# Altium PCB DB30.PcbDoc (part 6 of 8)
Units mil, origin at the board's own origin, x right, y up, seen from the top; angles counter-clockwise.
Board outline 3236.22 x 4456.69 mil, 8 copper layers (Top Layer, MidLayer1, MidLayer2, GND-Layer5, MidLayer3, VCC, MidLayer4, Bottom Layer), stack 61.8 mil thick; 219 components, 472 nets, 1811 pads, 1561 vias.
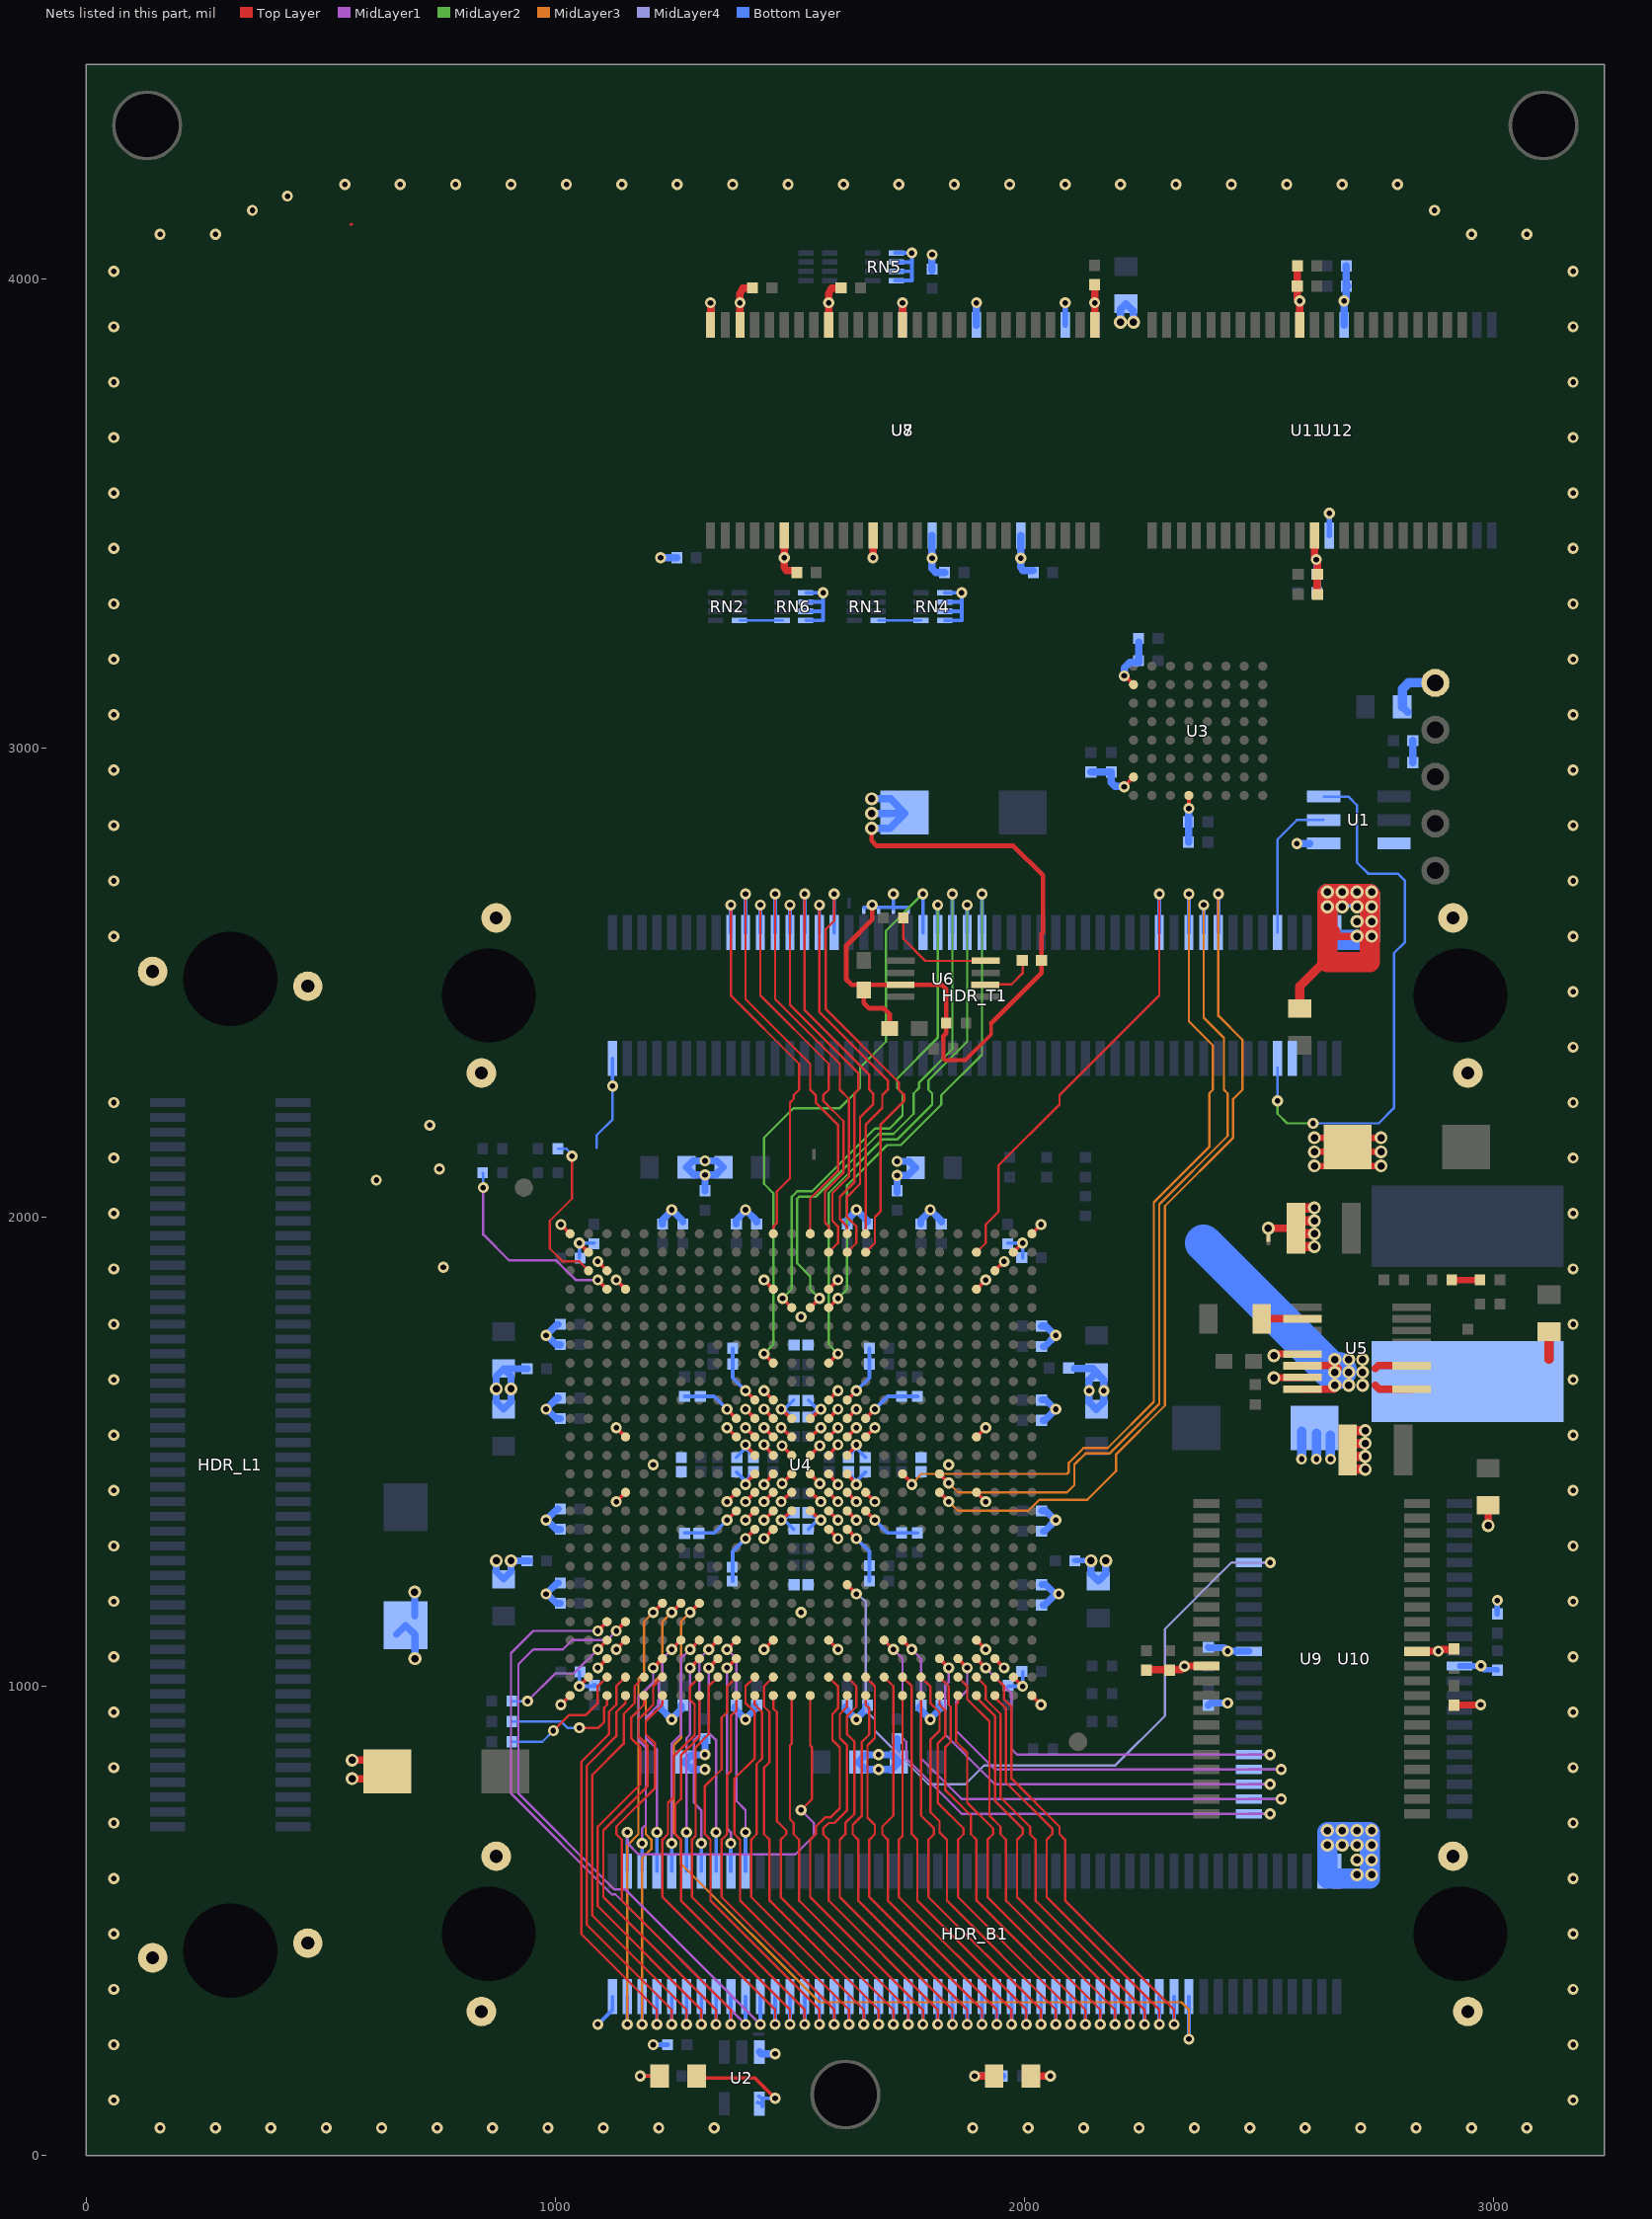
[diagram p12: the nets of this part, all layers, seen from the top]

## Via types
v1: diameter 23.62, hole 11.81, Top Layer to Bottom Layer, 944 vias
v2: diameter 23.62, hole 11.81, Top Layer to Bottom Layer, tented both sides, 477 vias
v3: diameter 27.56, hole 15.75, Top Layer to Bottom Layer, 139 vias
v4: diameter 23.62, hole 11.81, Top Layer to Bottom Layer, tented top, 1 vias

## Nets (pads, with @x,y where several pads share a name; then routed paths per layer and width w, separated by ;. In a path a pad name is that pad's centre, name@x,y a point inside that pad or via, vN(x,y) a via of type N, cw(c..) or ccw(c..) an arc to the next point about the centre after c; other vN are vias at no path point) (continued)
GND: C1.1 C2.2 C3.2 C4.2 C5.2 C6.2 C7.2 C8.2 C9.2 C10.2 C11.2 C12.2 C13.2 C14.2 C15.2 C16.2 C17.2 C18.2 C19.2 C20.2 C21.2 C22.2 C23.2 C24.2 C25.2 C26.2 C27.2 C28.2 C29.2 C30.2 C31.2 C32.2 C33.2 C34.2 C35.2 C36.2 C37.2 C38.2 C39.2 C40.2 C41.2 C42.2 C43.2 C44.2 C45.2 C46.2 C47.2 C48.2 C49.2 C50.2 C51.2 C52.2 C53.2 C54.2 C55.2 C56.2 C57.2 C58.2 C59.2 C60.2 C61.2 C62.2 C63.2 C64.2 C65.2 C66.2 C67.2 C68.2 C69.2 C70.2 C71.2 C72.2 C73.2 C74.2 C75.2 C76.2 C77.2 C78.2 C79.2 C80.2 C81.2 C82.2 C83.2 C84.2 C85.2 C86.2 C87.2 C88.2 C89.2 C90.2 C91.2 C92.2 C93.2 C94.2 C95.2 C96.2 C97.2 C98.2 C99.2 C100.2 C101.2 C102.2 C103.2 C104.2 C105.2 C106.2 C107.2 C108.1 C109.2 C110.2 C111.2 C112.2 C113.2 C114.2 C115.2 C116.2 C119.2 C120.2 C121.2 C122.2 C123.2 C125.2 C126.2 C127.2 C128.2 C129.2 C130.2 C131.2 C132.2 C133.2 C134.2 C135.2 C136.2 C137.2 C138.2 C139.2 C140.2 C141.2 C142.2 C143.2 C144.2 C145.2 C146.2 C147.2 C148.2 C149.2 C150.2 C151.2 HDR_B1.1 HDR_B1.98 HDR_B1.100 HDR_B1.MH1 HDR_B1.MH2 HDR_B1.MH3 HDR_B1.MH4 HDR_L1.MH1 HDR_L1.MH2 HDR_L1.MH3 HDR_L1.MH4 HDR_T1.1 HDR_T1.98 HDR_T1.100 HDR_T1.MH1 HDR_T1.MH2 HDR_T1.MH3 HDR_T1.MH4 LED2.2 NT4.2 NT5.2 NT6.2 NT7.2 NT8.2 R25.2 RN4.1 RN4.2 RN4.3 RN4.4 RN5.1 RN5.2 RN5.3 RN5.4 RN6.1 RN6.2 RN6.3 RN6.4 TP1.1 U1.1 U2.3 U3.E8 U3.H2 U3.H7 U4.A1 U4.A26 U4.AC4 U4.AC12 U4.AC15 U4.AC23 U4.AD3 U4.AD24 U4.AE2 U4.AE25 U4.AF1 U4.AF26 U4.B2 U4.B25 U4.C3 U4.C24 U4.D4 U4.D12 U4.D15 U4.D23 U4.K11 U4.K12 U4.K15 U4.K16 U4.L10 U4.L11 U4.L12 U4.L13 U4.L14 U4.L15 U4.L16 U4.L17 U4.M4 U4.M10 U4.M11 U4.M12 U4.M13 U4.M14 U4.M15 U4.M16 U4.M17 U4.M23 U4.N11 U4.N12 U4.N13 U4.N14 U4.N15 U4.N16 U4.P11 U4.P12 U4.P13 U4.P14 U4.P15 U4.P16 U4.R4 U4.R10 U4.R11 U4.R12 U4.R13 U4.R14 U4.R15 U4.R16 U4.R17 U4.R23 U4.T10 U4.T11 U4.T12 U4.T13 U4.T14 U4.T15 U4.T16 U4.T17 U4.U11 U4.U12 U4.U15 U4.U16 U5.13 U5.15 U6.3 U7.6 U7.12 U7.28 U7.41 U7.46 U7.52 U7.54 U8.6 U8.12 U8.28 U8.41 U8.46 U8.52 U8.54 U9.12 U9.34 U10.12 U10.34 U11.12 U11.34 U12.12 U12.34 | length 15039.3
  Top Layer w5: 564,4116 566,4116
  Top Layer w7.87: v1(1011.81,960.63) U4.AF1@1031.5,980.31 ; v1(1011.81,1984.25) U4.A1@1031.5,1964.57 ; v1(1051.18,1000) U4.AE2@1070.87,1019.68 ; v1(1051.18,1944.88) U4.B2@1070.87,1925.2 ; v1(1090.55,1039.37) U4.AD3@1110.24,1059.05 ; v1(1090.55,1905.51) U4.C3@1110.24,1885.83 ; v1(1129.92,1078.74) U4.AC4@1149.61,1098.43 ; v1(1129.92,1393.7) U4.R4@1149.61,1413.39 ; v1(1129.92,1551.18) U4.M4@1149.61,1531.5 ; v1(1129.92,1866.14) U4.D4@1149.61,1846.46 ; v1(1366.14,1354.33) U4.T10@1385.83,1374.02 ; v1(1366.14,1393.7) U4.R10@1385.83,1413.39 ; v1(1366.14,1551.18) U4.M10@1385.83,1531.5 ; v1(1366.14,1590.55) U4.L10@1385.83,1570.87 ; v1(1405.51,1314.96) U4.U11@1425.2,1334.65 ; v1(1405.51,1354.33) U4.T11@1425.2,1374.02 ; v1(1405.51,1393.7) U4.R11@1425.2,1413.39 ; v1@1405.51,1433.07 U4.P11@1425.2,1452.76 ; v1(1405.51,1514.76) U4.N11@1425.2,1492.13 ; v1(1405.51,1551.18) U4.M11@1425.2,1531.5 ; v1(1405.51,1590.55) U4.L11@1425.2,1570.87 ; v1(1405.51,1629.92) U4.K11@1425.2,1610.24 ; v1(1444.88,1078.74) U4.AC12@1464.57,1098.43 ; v1(1444.88,1314.96) U4.U12@1464.57,1334.65 ; v1(1444.88,1354.33) U4.T12@1464.57,1374.02 ; v1(1444.88,1393.7) U4.R12@1464.57,1413.39 ; v1(1444.88,1430.12) U4.P12@1464.57,1452.76 ; v1(1444.88,1514.76) U4.N12@1464.57,1492.13 ; v1(1444.88,1551.18) U4.M12@1464.57,1531.5 ; v1(1444.88,1590.55) U4.L12@1464.57,1570.87 ; v1(1444.88,1629.92) U4.K12@1464.57,1610.24 ; v1(1444.88,1866.14) U4.D12@1464.57,1846.46 ; v1(1481.3,1354.33) U4.T13@1503.94,1374.02 ; v1(1481.3,1393.7) U4.R13@1503.94,1413.39 ; v1(1481.3,1551.18) U4.M13@1503.94,1531.5 ; v1(1481.3,1590.55) U4.L13@1503.94,1570.87 ; v1(1483.27,1432.09) U4.P13@1503.94,1452.76 ; v1(1483.27,1512.8) U4.N13@1503.94,1492.13 ; U4.T14@1543.31,1374.02 v1(1565.94,1354.33) ; U4.R14@1543.31,1413.39 v1(1565.94,1393.7) ; U4.P14@1543.31,1452.76 v1(1563.98,1432.09) ; U4.N14@1543.31,1492.13 v1(1563.98,1512.8) ; U4.M14@1543.31,1531.5 v1(1565.94,1551.18) ; U4.L14@1543.31,1570.87 v1(1565.94,1590.55) ; U4.AC15@1582.68,1098.43 v1(1602.36,1078.74) ; U4.U15@1582.68,1334.65 v1(1602.36,1314.96) ; U4.T15@1582.68,1374.02 v1(1602.36,1354.33) ; U4.R15@1582.68,1413.39 v1(1602.36,1393.7) ; U4.P15@1582.68,1452.76 v1(1602.36,1430.12) ; U4.N15@1582.68,1492.13 v1(1602.36,1514.76) ; U4.M15@1582.68,1531.5 v1(1602.36,1551.18) ; U4.L15@1582.68,1570.87 v1(1602.36,1590.55) ; U4.K15@1582.68,1610.24 v1(1602.36,1629.92) ; U4.D15@1582.68,1846.46 v1(1602.36,1866.14) ; U4.U16@1622.05,1334.65 v1(1641.73,1314.96) ; U4.T16@1622.05,1374.02 v1(1641.73,1354.33) ; U4.R16@1622.05,1413.39 v1(1641.73,1393.7) ; U4.P16@1622.05,1452.76 v1(1641.73,1430.12) ; U4.N16@1622.05,1492.13 v1(1641.73,1514.76) ; U4.M16@1622.05,1531.5 v1(1641.73,1551.18) ; U4.L16@1622.05,1570.87 v1(1641.73,1590.55) ; U4.K16@1622.05,1610.24 v1(1641.73,1629.92) ; U4.T17@1661.42,1374.02 v1(1681.1,1354.33) ; U4.R17@1661.42,1413.39 v1(1681.1,1393.7) ; U4.M17@1661.42,1531.5 v1(1681.1,1551.18) ; U4.L17@1661.42,1570.87 v1(1681.1,1590.55) ; U4.AC23@1897.64,1098.43 v1(1917.32,1078.74) ; U4.R23@1897.64,1413.39 v1(1917.32,1393.7) ; U4.M23@1897.64,1531.5 v1(1917.32,1551.18) ; U4.D23@1897.64,1846.46 v1(1917.32,1866.14) ; U4.AD24@1937.01,1059.05 v1(1956.69,1039.37) ; U4.C24@1937.01,1885.83 v1(1956.69,1905.51) ; U4.AE25@1976.38,1019.68 v1(1996.06,1000) ; U4.B25@1976.38,1925.2 v1(1996.06,1944.88) ; U4.AF26@2015.75,980.31 v1(2035.43,960.63) ; U4.A26@2015.75,1964.57 v1(2035.43,1984.25) ; v1@2212.6,2918.31 U3.H7@2232.28,2937.99 ; v1@2212.6,3154.53 U3.H2@2232.28,3134.84 ; v1(2350.4,2871.07) U3.E8@2350.39,2898.62
  Top Layer w8: 1826.77,2377.95 1827.63,2377.09 1827.63,2337.72 1830.71,2334.65 1874.02,2334.65 1929.13,2389.76 1929.13,2413.38
  Top Layer w10: C126.2@1657.48,2484.25 1657.48,2456.7 1669.29,2444.88 1700.79,2444.88 1712.59,2433.07 C125.2@1712.59,2409.44 ; C126.2@1664.36,2495.07 1823.82,2495.07 1833.15,2485.75 1833.15,2392.2 1826.77,2385.83 1826.77,2377.95 ; v3(1674.21,2828.74) 1674.21,2802.16 1685.04,2791.33 1976.37,2791.33 2039.37,2728.34 2039.37,2606.29 2036.41,2603.34 2036.41,2520.67 1929.13,2413.38 ; v2(1675.2,2665.35) 1675.2,2633.86 1620.08,2578.74 1620.08,2506.89 1631.89,2495.07 1678.15,2495.07
  Top Layer w13.78: v3(2618.11,2109.29) C119.2@2669.08,2109.29 ; v3(2618.11,2139.29) C119.2@2669.08,2139.29 ; v3(2618.11,2169.29) C119.2@2669.08,2169.29 ; C119.2@2709.01,2109.29 v3(2759.99,2109.29) ; C119.2@2709.01,2139.29 v3(2759.99,2139.29) ; C119.2@2709.01,2169.29 v3(2759.99,2169.29)
  Top Layer w15: C139.2@2259.84,1034.45 2260.82,1035.43 2334.65,1035.43 2341,1041.79 v1(2341,1043) 2341.3,1043.3 U9.34@2387.89,1043.3 ; v3(2531.5,1657.48) 2532.26,1658.25 U5.15@2591.08,1658.25 ; v3(2531.5,1704.72) 2535.43,1708.66 U5.13@2590.55,1708.66 ; U9.12@2836.71,1074.8 2881.8,1074.8 v1(2882,1075) 2886.02,1075 2889.76,1078.74 2914.47,1078.74 C136.2@2915.44,1079.71 ; C138.2@2915.3,957.92 2917.32,957.76 2914.45,960.63 v1(2972.44,960.63)
  Top Layer w15.75: v3(566.93,803.15) 626.34,803.15 C23.2@641.81,818.62 617.91,842.52 v3(566.93,842.52) ; U7.54@1330.71,3901.57 v2(1330.71,3948.82) ; U7.52@1393.7,3901.57 v2(1393.7,3948.82) ; v2@1393.7,3944.88 1393.7,3964.57 ; 1393.7,3968.51 1399.61,3980.32 C132.2@1420.27,3980.31 ; C132.2@1416.34,3980.32 C132.2@1418.31,3978.34 ; U7.6@1488.19,3452.76 1488.19,3409.45 v2(1488.19,3405.51) 1488.19,3385.83 1492.13,3377.95 C129.2@1514.77,3377.95 ; U7.46@1582.68,3901.57 v2(1582.68,3948.82) ; v2@1582.68,3944.88 1582.68,3964.57 1582.68,3968.51 1588.58,3980.32 C133.2@1609.25,3980.31 ; v2(1677.17,3405.51) U7.12@1677.17,3452.76 ; U7.41@1740.16,3901.57 v2(1740.16,3948.82) ; LED2.2@2011.81,169.29 v1(2055.12,169.29) ; U7.28@2149.61,3901.57 C128.2@2149.6,3987.2 ; v3(2519.68,1976.38) C123.2@2582.67,1976.38 ; C145.2@2580.43,4028.54 C145.2@2580.57,4028.67 ; C145.2@2581.69,4027.55 2581.69,3957.68 v2(2586.61,3952.76) U11.34@2586.61,3901.57 ; U11.12@2618.11,3452.76 2618.11,3405.51 2624.72,3398.9 C148.2@2624.72,3370.07 C148.2@2625.71,3371.06 ; C144.2@2623.74,3329.72 2623.74,3370.07 C148.2@2623.77,3370.23 ; 2645.67,2598.43 v3(2708.66,2598.43) ; v3(2988.19,1342.52) C120.2@2988.18,1385.82
  Top Layer w19.68: C24.2@2586.61,2444.88 2586.61,2492.12 2649.61,2555.12 ; 3118.09,1696.83 C122.2@3118.1,1755.9
  Top Layer w20: C123.2@2578.73,1937 v3(2618.1,1937) ; C123.2@2578.73,1964.56 v3(2618.1,1964.56) ; C123.2@2578.73,1992.12 v3(2618.1,1992.12) ; C123.2@2578.73,2019.68 v3(2618.1,2019.68) ; C121.2@2687.01,1462.59 v3(2726.38,1462.59) ; C121.2@2687.01,1490.15 v3(2726.38,1490.15) ; C121.2@2687.01,1517.71 v3(2726.38,1517.71) ; C121.2@2687.01,1545.27 v3(2726.38,1545.27)
  Top Layer w39.37: 2645.67,2606.3 2653.54,2606.3
  Top Layer w43.31: 2645.67,2543.31 2736.22,2543.31 2736.22,2688.98 2645.67,2688.98 2645.67,2543.31
  Bottom Layer w5: 1087.87,2147.57 1087.87,2174.07 1122.05,2208.25 v2(1122.05,2279.53)
  Bottom Layer w7.87: C35.2@1051.18,1031.5 v1(1051.18,1000) C38.2@1082.68,1000 ; C41.2@1051.18,1913.39 v1(1051.18,1944.88) C33.2@1082.68,1944.88 ; v1@1082.68,1039.37 v1(1090.55,1039.37) v1@1090.55,1031.5 ; v1@1082.68,1905.51 v1(1090.55,1905.51) v1@1090.55,1913.38 ; v2(1090.55,279.53) 1122.05,311.02 HDR_B1.1@1122.05,338.58 ; v2(1122.05,2279.53) HDR_T1.1@1122.05,2338.58 ; v1(1248.03,2015.75) v1@1251.97,2015.75 ; C19.2@1275.59,1326.77 1311.02,1326.77 1338.58,1326.77 v1(1366.14,1354.33) ; C13.2@1275.59,1618.11 1276.38,1618.11 1306.51,1618.11 1338.58,1618.11 v1(1366.14,1590.55) ; C20.2@1377.95,1224.41 1377.95,1228.34 1377.95,1253.94 1377.95,1287.4 v1(1405.51,1314.96) ; C18.2@1377.95,1720.47 C14.2@1377.95,1687.01 1377.95,1657.48 v1(1405.51,1629.92) ; C66.2@1385.83,1456.69 1405.51,1437.01 C95.2@1425.2,1456.69 ; C93.2@1385.83,1488.19 v1@1405.51,1507.87 ; v1(1405.51,1514.76) v1@1405.51,1507.88 ; C94.2@1425.2,1488.19 v1@1405.51,1507.88 ; v1(1481.3,1354.33) v1@1488.19,1354.33 ; C88.2@1507.87,1334.65 v1@1488.19,1354.33 ; C82.2@1507.87,1374.02 v1@1488.19,1354.33 ; C73.2@1507.87,1570.87 1488.19,1590.55 C67.2@1507.87,1610.24 ; RN6.4@1534.64,3271.65 1570.87,3271.65 v1(1570.87,3330.71) RN6.1@1534.64,3330.71 ; RN6.3@1534.64,3291.34 1570.87,3291.34 ; RN6.2@1534.64,3311.02 1570.87,3311.02 ; C92.2@1539.37,1334.65 v1@1559.06,1354.33 ; C98.2@1539.37,1374.02 v1@1559.06,1354.33 ; C74.2@1539.37,1570.87 v1@1559.06,1590.55 ; C75.2@1539.37,1610.24 v1@1559.05,1590.55 ; v1(1565.94,1354.33) v1@1559.06,1354.33 ; v1(1565.94,1590.55) v1@1559.06,1590.55 ; C90.2@1622.05,1456.69 v1@1641.73,1437.01 ; C78.2@1622.05,1488.19 v1@1641.73,1507.87 ; v1(1641.73,1314.96) 1669.29,1287.4 C7.2@1669.29,1256.89 C15.2@1669.29,1224.41 ; v1(1641.73,1430.12) v1@1641.73,1437.01 ; v1(1641.73,1514.76) v1@1641.73,1507.87 ; v1(1641.73,1629.92) 1669.29,1657.48 1669.29,1688.98 C21.2@1669.29,1720.47 ; NT7.2@1657.48,2660.43 NT4.2@1751.97,2660.43 ; C77.2@1661.42,1456.69 v1@1641.73,1437.01 ; C72.2@1661.42,1488.19 v1@1641.73,1507.87 ; v1(1681.1,1354.33) 1708.66,1326.77 1744.09,1326.77 1771.06,1326.77 C8.2@1771.65,1326.77 ; v1(1681.1,1590.55) 1708.66,1618.11 C17.2@1738.19,1618.11 C10.2@1771.65,1618.11 ; NT5.2@1720.47,2657.48 v2(1720.47,2688.98) ; RN5.4@1723.62,3996.06 1759.84,3996.06 v1(1759.84,4055.12) RN5.1@1723.62,4055.12 ; RN5.3@1723.62,4015.75 1759.84,4015.75 ; RN5.2@1723.62,4035.43 1759.84,4035.43 ; C51.2@1771.65,952.76 C51.2@1772.14,952.26 ; RN4.4@1829.92,3271.65 1866.14,3271.65 v1(1866.14,3330.71) RN4.1@1829.92,3330.71 ; RN4.3@1829.92,3291.34 1866.14,3291.34 ; RN4.2@1829.92,3311.02 1866.14,3311.02 ; C31.2@1964.57,1000 v1(1996.06,1000) C36.2@1996.06,1031.5 ; C34.2@1964.57,1944.88 v1(1996.06,1944.88) C37.2@1996.06,1913.39
  Bottom Layer w9.84: v1(1208.66,236.22) C108.1@1239.17,236.22
  Bottom Layer w11.81: C38.2@1083.25,1001.71 C38.2@1083.47,1001.49 ; U8.52@2086.61,3901.57 v2(2086.61,3948.82) ; C39.2@2107.28,1267.71 v3(2141.73,1267.72) ; U8.54@2149.61,3901.57 v2(2149.61,3948.82) ; U12.12@2649.61,3452.76 v2(2649.61,3500) ; U10.34@2927.25,1043.3 v1@2972.3,1043.3 ; v1(2973,1044) v1@2972.3,1043.3 ; C143.2@3007.87,1034.45 3006.88,1035.43 2979.33,1035.43 2972.3,1042.47 v1@2972.3,1043.3 ; C141.2@3007.87,1154.53 v1(3007.87,1183.07)
  Bottom Layer w15: C106.2@661.42,1110.59 C106.2@680.83,1130 700.79,1110.04 v3(700.79,1059.06) ; C106.2@700.23,1149.41 v3(700.23,1200.94) ; v3(874.02,1267.72) 874.02,1244.09 C45.2@889.76,1228.34 905.51,1244.09 v3(905.51,1267.72) C28.2@944.88,1267.72 ; C32.2@939.96,1677.16 C43.2@889.76,1677.16 ; v1(980.31,1196.85) 1003.94,1220.48 C56.2@1006.89,1220.48 ; v1(980.31,1354.33) 1003.94,1377.96 C101.2@1006.89,1377.96 ; v1(980.31,1590.55) 1003.94,1614.18 C102.2@1006.89,1614.18 ; v1(980.31,1748.03) 1003.94,1771.66 C104.2@1006.89,1771.66 ; v1@984.31,1194.81 1002.24,1176.88 C84.2@1010.54,1176.88 ; v1@984.31,1352.29 1002.24,1334.36 C53.2@1010.54,1334.36 ; v1@984.31,1588.51 1002.24,1570.58 C58.2@1010.54,1570.58 ; v1@984.31,1745.99 1002.24,1728.07 C61.2@1010.54,1728.07 ; C62.2@1224.4,955.71 1224.4,952.76 v1(1248.03,929.13) ; C59.2@1228.06,1985.52 1228.06,1993.82 v1@1245.99,2011.75 ; v1(1248.03,2015.75) 1271.66,1992.12 C70.2@1271.66,1989.17 ; v1@1250.07,933.13 1268,951.06 C85.2@1268,959.36 ; v2(1318.9,822.83) 1291.33,822.83 C49.2@1275.59,838.58 1291.34,854.33 v2(1318.9,854.33) C40.2@1318.89,888.78 ; C29.2@1318.89,2056.1 1318.89,2089.89 v1(1319.02,2090) ; C83.2@1381.88,955.71 1381.88,952.76 v1(1405.51,929.13) ; C100.2@1385.54,1985.52 1385.54,1993.82 v1@1403.47,2011.75 ; v1(1405.51,2015.75) 1429.14,1992.12 C65.2@1429.14,1989.17 ; v1@1407.55,933.13 1425.48,951.06 C57.2@1425.48,959.36 ; C52.2@1618.11,955.71 1618.11,952.76 v1(1641.73,929.13) ; C99.2@1621.77,1985.52 1621.77,1993.82 v1@1639.69,2011.75 ; v1(1641.73,2015.75) 1665.36,1992.12 C64.2@1665.36,1989.17 ; v1@1643.77,933.13 1661.7,951.06 C91.2@1661.7,959.36 ; C48.2@1728.34,850.4 C30.2@1728.34,888.78 ; C26.2@1728.34,2052.41 v1@1728.34,2092.69 ; v1@1728.34,2085.06 v1(1728.58,2089.02) 1751.54,2089 C44.2@1767.84,2105.29 1754.13,2119 v1(1728.58,2119.02) ; C51.2@1775.59,955.71 1775.59,952.76 v1(1799.21,929.13) ; C68.2@1779.25,1985.52 1779.25,1993.82 v1@1797.18,2011.75 ; v1(1799.21,2015.75) 1822.84,1992.12 C60.2@1822.84,1989.17 ; v1@1801.25,933.13 1819.18,951.06 C69.2@1819.18,959.36 ; C89.2@2036.41,1767.71 2036.7,1768 2045,1768 2062.93,1750.07 2066.93,1750.07 v1(2066.93,1748.03) 2043.3,1724.41 C54.2@2040.35,1724.41 ; C103.2@2036.7,1216.82 2045,1216.82 v1@2062.93,1198.89 ; C55.2@2036.7,1374.3 2045,1374.3 v1@2062.93,1356.37 ; C71.2@2036.7,1610.52 2045,1610.52 v1@2062.93,1592.59 ; C50.2@2040.35,1173.22 2043.3,1173.22 v1@2066.93,1196.85 ; C63.2@2040.35,1566.93 2043.3,1566.93 v1(2066.93,1590.55) ; C105.2@2040.64,1331 2040.35,1330.71 2043.3,1330.7 v1(2066.93,1354.33) ; v1@2069.99,1194.01 v1(2072.99,1197.01) ; C140.2@2391.82,959.64 2396.75,964.57 v1(2433.07,964.57) ; C142.2@2391.82,1083.65 2392.8,1082.68 2425.2,1082.68 2432.87,1075 v1(2433,1075) 2433.21,1074.79 U10.12@2478.44,1074.79 ; C43.2@889.76,1677.16 874.02,1661.42 874.02,1606.29 C4.2@889.76,1590.55 905.51,1606.3 905.51,1661.41 C43.2@889.76,1677.16 ; C42.2@1279.53,2106.29 1295.93,2089.89 1341.86,2089.89 C25.2@1358.26,2106.29 1344.56,2120 1293.23,2120 C42.2@1279.53,2106.29 ; C5.2@1645.67,838.58 1661.41,822.83 1716.53,822.83 C48.2@1732.28,838.58 1716.53,854.33 1661.42,854.33 C5.2@1645.67,838.58
  Bottom Layer w15.75: v2(1224.41,3405.51) C130.2@1258.85,3405.51 ; U8.28@1330.71,3901.57 v2@1330.71,3944.88 ; U2.3@1435.04,220.47 1438.97,216.54 v1(1468.5,216.54) ; v3(1674.21,2828.74) 1713.39,2828.74 1745.15,2860.51 1713.93,2891.73 v3(1674.21,2891.73) ; v3(1674.21,2860.24) C107.2@1744.88,2860.24 ; U8.41@1740.16,3901.57 v2(1740.16,3948.82) ; U8.12@1803.15,3452.76 1803.15,3405.51 v2(1803.15,3404.53) 1803.15,3381.89 1811.04,3374.01 C135.2@1829.72,3374.01 ; C131.2@1803.15,4016.72 1803.15,4047.24 v2(1803.15,4051.18) ; U8.46@1897.64,3901.57 v2(1897.64,3948.82) v2@1897.64,3944.88 ; U8.6@1992.13,3452.76 1992.13,3385.83 1996.06,3377.95 C134.2@2018.71,3377.95 ; 2107.28,1677.16 2145.66,1677.16 2169.29,1653.54 2169.29,1606.3 C6.2@2153.54,1590.55 2137.8,1606.29 2137.8,1653.54 C46.2@2153.54,1669.29 ; v3(2141.73,1267.72) 2141.73,1240.15 C47.2@2157.48,1224.41 2161.42,1228.35 2173.23,1240.16 v3(2173.23,1267.72) ; C114.2@2141.73,2948.82 C111.2@2185.04,2948.82 2185.04,2926.19 2192.92,2918.31 v1@2212.6,2918.31 ; v3(2204.72,3907.48) 2204.72,3935.04 C116.2@2216.53,3946.84 2232.28,3931.1 v3(2232.28,3907.48) ; v1(2212.6,3153.54) 2212.6,3170.28 2224.41,3182.09 2243.11,3182.09 C110.2@2243.11,3225.39 ; C109.2@2349.4,2799.21 2350.4,2800.2 v1(2350.4,2871.07) ; v2(2580.71,2796.26) 2608.06,2796.26 U1.1@2608.25,2796.45 ; v2(2622.05,3401.57) 2623.03,3400.6 C146.2@2623.03,3330.7 ; v2@2681.1,3956.7 v2(2681.1,3952.76) 2686.02,3957.67 C151.2@2686.02,3984.25 ; U12.34@2681.38,3901.57 v2@2681.38,3944.88 ; C147.2@2686.02,4027.55 2686.02,3987.2 C151.2@2688.98,3984.25 ; C115.2@2805.12,3087.59 C115.2@2816.93,3075.79 ; C2.2@2827.75,2968.5 C1.1@2827.75,3015.74
  Bottom Layer w20: v1(2590.55,1484.25) C3.2@2590.55,1543.31 ; v1(2622.05,1484.25) C3.2@2622.05,1539.37 ; v1(2652.34,1484.25) C3.2@2652.34,1535.44 ; C115.2@2805.12,3087.59 2805.12,3125.12 2818.67,3138.67 TP1.1@2875.71,3138.67
  Bottom Layer w43.31: v3@2649.61,681.1 v3@2736.22,681.1 ; v3@2649.61,2681.1 v3@2736.22,2681.1 ; v3@2736.22,681.1 2736.22,688.98 2645.67,688.98 2645.67,590.55 2736.22,590.55 2736.22,598.42 2736.22,629.92 2736.22,661.42 v3@2736.22,681.1 ; v3@2736.22,2681.1 2736.22,2688.98 2645.67,2688.98 2645.67,2590.55 2736.22,2590.55 2736.22,2598.43 2736.22,2629.92 2736.22,2661.42 v3@2736.22,2681.1
  other v1: 157.48,59.06 275.59,59.06 393.7,59.06 511.81,59.06 629.92,59.06 748.03,59.06 866.14,59.06 984.25,59.06 1102.36,59.06 1220.47,59.06 1338.58,59.06 1889.76,59.06 2007.87,59.06 2125.98,59.06 2244.09,59.06 2362.2,59.06 2480.31,59.06 2598.43,59.06 2716.54,59.06 2834.65,59.06 2952.76,59.06 3070.87,59.06 59.06,118.11 3169.29,118.11 59.06,236.22 3169.29,236.22 59.06,354.33 3169.29,354.33 59.06,472.44 3169.29,472.44 59.06,590.55 3169.29,590.55 59.06,708.66 3169.29,708.66 1688.98,822.83 59.06,826.77 3169.29,826.77 1688.98,854.33 59.06,944.88 3169.29,944.88 59.06,1062.99 3169.29,1062.99 1523.62,1157.48 59.06,1181.1 3169.29,1181.1 59.06,1299.21 3169.29,1299.21 59.06,1417.32 3169.29,1417.32 1405.51,1430.12 1208.66,1472.44 1838.58,1472.44 59.06,1535.43 3169.29,1535.43 2137.8,1629.92 2169.29,1629.92 59.06,1653.54 3169.29,1653.54 59.06,1771.65 3169.29,1771.65 1523.62,1787.4 59.06,1889.76 3169.29,1889.76 761.3,1893.2 59.06,2007.87 3169.29,2007.87 618.5,2078.9 753,2102.5 1319.02,2120 59.06,2125.98 3169.29,2125.98 732.5,2196 59.06,2244.09 3169.29,2244.09 3169.29,2362.2 3169.29,2480.32 59.06,2598.43 3169.29,2598.43 59.06,2716.54 3169.29,2716.54 59.06,2834.65 3169.29,2834.65 2212.6,2917.32 59.06,2952.76 3169.29,2952.76 59.06,3070.87 3169.29,3070.87 59.06,3188.98 3169.29,3188.98 59.06,3307.09 3169.29,3307.09 59.06,3425.2 3169.29,3425.2 59.06,3543.31 3169.29,3543.31 59.06,3661.42 3169.29,3661.42 59.06,3779.53 3169.29,3779.53 59.06,3897.64 3169.29,3897.64 59.06,4015.75 3169.29,4015.75 157.48,4094.49 275.59,4094.49 2952.76,4094.49 3070.87,4094.49 354.33,4145.67 2874.02,4145.67 429,4176 551.18,4200.79 669.29,4200.79 787.4,4200.79 905.51,4200.79 1023.62,4200.79 1141.73,4200.79 1259.84,4200.79 1377.95,4200.79 1496.06,4200.79 1614.17,4200.79 1732.28,4200.79 1850.39,4200.79 1968.5,4200.79 2086.61,4200.79 2204.72,4200.79 2322.83,4200.79 2440.94,4200.79 2559.06,4200.79 2677.17,4200.79 2795.28,4200.79
  other v2: 1992.13,3404.53
  other v3: 2708.66,598.42 2740.16,598.42 2708.66,629.92 2740.16,629.92 2645.67,661.42 2677.17,661.42 2708.66,661.42 2740.16,661.42 2645.67,692.91 2677.17,692.91 2708.66,692.91 2740.16,692.91 874.02,1633.86 905.51,1633.86 2740.16,2598.43 2708.66,2629.92 2740.16,2629.92 2645.67,2661.42 2677.17,2661.42 2708.66,2661.42 2740.16,2661.42 2645.67,2692.91 2677.17,2692.91 2708.66,2692.91 2740.16,2692.91
HSWAP_EN: R4.2 U4.C2 | length 357.5
  Top Layer w5: v1(1035.43,2129.92) 1035.43,2039.43 988.19,1992.19 988.19,1933.07 1015.75,1905.51 1051.18,1905.51 U4.C2@1070.87,1885.83
  Bottom Layer w5: R4.2@1005.43,2145.66 1023.62,2145.67 1035.43,2133.86 v1(1035.43,2129.92)
IO0: HDR_B1.7 U4.AE4 | length 905.2
  Top Layer w5: U4.AE4@1149.61,1019.68 1129.92,1000 1129.92,960.63 1114.17,944.88 1114.17,917.32 1114.17,905.51 1114.17,897.64 1055.12,838.58 1055.12,472.44 1216.54,311.02 v2(1216.54,279.53)
  Bottom Layer w7.87: v2(1216.54,279.53) HDR_B1.7@1216.54,338.58
IO1: HDR_B1.9 U4.AF4 | length 869.1
  Top Layer w5: U4.AF4@1149.61,980.31 1149.61,964.57 1129.92,944.88 1129.92,917.32 1129.92,905.51 1129.92,893.7 1066.93,830.71 1066.93,492.13 1248.03,311.02 v2(1248.03,279.53)
  Bottom Layer w7.87: v2(1248.03,279.53) HDR_B1.9@1248.03,338.58
IO2: HDR_B1.11 U4.AE5 | length 928
  Top Layer w5: U4.AE5@1188.98,1019.68 1169.29,1000 1169.29,964.57 1145.67,940.94 1145.67,917.32 1145.67,905.51 1145.67,877.95 1078.74,811.02 1078.74,511.81 1279.53,311.02 v2(1279.53,279.53)
  Bottom Layer w7.87: v2(1279.53,279.53) HDR_B1.11@1279.53,338.58
IO3: HDR_B1.13 U4.AF5 | length 908.2
  Top Layer w5: U4.AF5@1188.98,980.31 1188.98,960.63 1161.42,933.07 1161.42,917.32 1161.42,905.51 1161.42,889.76 1181.1,870.08 1181.1,791.34 1090.55,700.79 1090.55,531.5 1311.02,311.02 v2(1311.02,279.53)
  Bottom Layer w7.87: v2(1311.02,279.53) HDR_B1.13@1311.03,338.58
IO4: HDR_B1.15 U4.AE6 | length 967.2
  Top Layer w5: U4.AE6@1228.35,1019.68 1208.66,1000 1208.66,996.06 1208.66,964.57 1208.66,960.63 1196.85,948.82 1177.17,929.13 1177.17,917.32 1177.17,905.51 1177.17,893.7 1196.85,874.02 1196.85,787.4 1102.36,692.91 1102.36,551.18 1342.52,311.02 v2(1342.52,279.53)
  Bottom Layer w7.87: v2(1342.52,279.53) HDR_B1.15@1342.52,338.58
IO5: HDR_B1.17 U4.AF6 | length 918
  Top Layer w5: U4.AF6@1228.35,980.31 1228.35,960.63 1192.91,925.2 1192.91,917.32 1192.91,905.51 1192.91,897.64 1212.6,877.95 1212.6,783.46 1129.92,700.79 1129.92,685.04 1141.73,673.23 1141.73,543.31 1374.02,311.02 v2(1374.02,279.53)
  Bottom Layer w7.87: v2(1374.02,279.53) HDR_B1.17@1374.02,338.58
IO6: HDR_B1.19 U4.AB3 | length 1294.6
  Top Layer w7.87: v1(1090.55,1118.11) U4.AB3@1110.24,1137.8
  MidLayer1 w5: v1(1090.55,1118.11) 968.5,1118.11 952.76,1118.11 905.51,1070.87 905.51,771.65 1120.32,556.84 1128.2,556.84 v2(1405.51,279.53)
  Bottom Layer w7.87: v2(1405.51,279.53) HDR_B1.19@1405.51,338.58
IO7: HDR_B1.21 U4.AB4 | length 1320.1
  Top Layer w7.87: v1(1129.92,1118.11) U4.AB4@1149.61,1137.8
  MidLayer1 w5: v1(1129.92,1118.11) 1110.24,1098.43 1035.43,1098.43 1015.75,1078.74 968.5,1078.74 952.76,1078.74 921.26,1047.24 921.26,771.65 1125.98,566.93 1149.61,566.93 v2(1437.01,279.53)
  Bottom Layer w7.87: v2(1437.01,279.53) HDR_B1.21@1437.01,338.58
IO8: HDR_B1.23 U4.AE8 | length 939.3
  Top Layer w5: U4.AE8@1307.09,1019.68 1287.4,1000 1287.4,971.17 1297.09,961.49 1297.09,896.24 1251.97,851.12 1251.97,763.78 1240.16,751.97 1240.16,685.04 1228.35,673.23 1228.35,551.18 1468.5,311.02 v2(1468.5,279.53)
  Bottom Layer w7.87: v2(1468.5,279.53) HDR_B1.23@1468.51,338.58
IO9: HDR_B1.25 U4.AF8 | length 882.2
  Top Layer w5: U4.AF8@1307.09,980.31 1307.09,917.32 1307.09,905.51 1307.09,892.09 1267.72,852.72 1267.72,759.84 1255.91,748.03 1255.91,685.04 1267.72,673.23 1267.72,543.31 1500,311.02 v2(1500,279.53)
  Bottom Layer w7.87: v2(1500,279.53) HDR_B1.25@1500,338.58
IO10: HDR_B1.27 U4.AE9 | length 921.5
  Top Layer w5: U4.AE9@1346.46,1019.68 1326.77,1000 1326.77,917.32 1326.77,905.51 1326.77,897.64 1299.21,870.08 1299.21,681.1 1291.34,673.23 1291.34,551.18 1531.5,311.02 v2(1531.5,279.53)
  Bottom Layer w7.87: v2(1531.5,279.53) HDR_B1.27@1531.5,338.58
IO11: HDR_B1.29 U4.AE10 | length 928
  Top Layer w5: U4.AE10@1385.83,1019.68 1366.14,1000 1366.14,944.88 1354.33,933.07 1354.33,917.32 1354.33,905.51 1354.33,822.83 1318.9,787.4 1318.9,685.04 1330.71,673.23 1330.71,543.31 1562.99,311.02 v2(1562.99,279.53)
  Bottom Layer w7.87: v2(1562.99,279.53) HDR_B1.29@1562.99,338.58
IO12: HDR_B1.31 U4.AF10 | length 872.4
  Top Layer w5: U4.AF10@1385.83,980.31 1385.83,948.82 1374.02,937.01 1374.02,917.32 1374.02,905.51 1374.02,818.9 1366.14,811.02 1366.14,803.15 1366.14,685.04 1354.33,673.23 1354.33,551.18 1594.49,311.02 v2(1594.49,279.53)
  Bottom Layer w7.87: v2(1594.49,279.53) HDR_B1.31@1594.49,338.58
IO13: HDR_B1.33 U4.AE11 | length 934.6
  Top Layer w5: U4.AE11@1425.2,1019.68 1405.51,1000 1405.51,964.57 1425.2,944.88 1425.2,917.32 1425.2,905.51 1425.2,846.46 1381.89,803.15 1381.89,685.04 1393.7,673.23 1393.7,543.31 1625.99,311.02 v2(1625.99,279.53)
  Bottom Layer w7.87: v2(1625.99,279.53) HDR_B1.33@1625.99,338.58
IO14: HDR_B1.35 U4.AF11 | length 875.6
  Top Layer w5: U4.AF11@1425.2,980.31 1425.2,960.63 1440.94,944.88 1440.94,917.32 1440.94,905.51 1440.94,846.46 1429.13,834.65 1429.13,685.04 1417.32,673.23 1417.32,551.18 1657.48,311.02 v2(1657.48,279.53)
  Bottom Layer w7.87: v2(1657.48,279.53) HDR_B1.35@1657.48,338.58
IO15: HDR_B1.37 U4.AE12 | length 918.3
  Top Layer w5: U4.AE12@1464.57,1019.68 1444.88,1000 1444.88,956.69 1456.69,944.88 1456.69,917.32 1456.69,905.51 1456.69,838.58 1444.88,826.77 1444.88,685.04 1456.69,673.23 1456.69,543.31 1688.98,311.02 v2(1688.98,279.53)
  Bottom Layer w7.87: v2(1688.98,279.53) HDR_B1.37@1688.98,338.58
IO16: HDR_B1.39 U4.AF12 | length 875.6
  Top Layer w5: U4.AF12@1464.57,980.31 1464.57,952.76 1472.44,944.88 1472.44,917.32 1472.44,905.51 1472.44,712.6 1492.13,692.91 1492.13,685.04 1480.31,673.23 1480.31,551.18 1720.47,311.02 v2(1720.47,279.53)
  Bottom Layer w7.87: v2(1720.47,279.53) HDR_B1.39@1720.48,338.58
IO17: HDR_B1.41 U4.AF13 | length 865.8
  Top Layer w5: U4.AF13@1503.94,980.31 1503.94,917.32 1503.94,901.57 1503.94,877.95 1500,874.02 1500,716.54 1507.87,708.66 1507.87,685.04 1519.68,673.23 1519.68,543.31 1751.97,311.02 v2(1751.97,279.53)
  Bottom Layer w7.87: v2(1751.97,279.53) HDR_B1.41@1751.97,338.58
IO18: HDR_B1.43 U4.AE15 | length 951.3
  Top Layer w5: U4.AE15@1582.68,1019.68 1602.36,1000 1602.36,952.76 1590.55,940.94 1590.55,917.32 1590.55,905.51 1590.55,885.83 1606.3,870.08 1606.3,740.16 1586.61,720.47 1574.8,720.47 1555.12,700.79 1555.12,685.04 1543.31,673.23 1543.31,551.18 1783.47,311.02 v2(1783.47,279.53)
  Bottom Layer w7.87: v2(1783.47,279.53) HDR_B1.43@1783.47,338.58
IO19: HDR_B1.45 U4.AF16 | length 907.7
  Top Layer w5: U4.AF16@1618.11,976.38 U4.AF16@1622.05,980.31 1622.05,956.69 1606.3,940.94 1606.3,917.32 1606.3,905.51 1606.3,889.76 1622.05,874.02 1622.05,736.22 1594.49,708.66 1582.68,708.66 1570.87,696.85 1570.87,685.04 1582.68,673.23 1582.68,543.31 1814.96,311.02 v2(1814.96,279.53)
  Bottom Layer w7.87: v2(1814.96,279.53) HDR_B1.45@1814.96,338.58
IO20: HDR_B1.47 U4.AE16 | length 934.6
  Top Layer w5: U4.AE16@1622.05,1019.68 1641.73,1000 1641.73,956.69 1622.05,937.01 1622.05,917.32 1622.05,905.51 1622.05,897.64 1637.8,881.89 1637.8,728.35 1618.11,708.66 1618.11,685.04 1606.3,673.23 1606.3,551.18 1846.46,311.02 v2(1846.46,279.53)
  Bottom Layer w7.87: v2(1846.46,279.53) HDR_B1.47@1846.46,338.58
IO21: HDR_B1.49 U4.AF17 | length 878.9
  Top Layer w5: U4.AF17@1661.42,980.31 1661.42,960.63 1669.29,952.76 1669.29,917.32 1669.29,905.51 1669.29,897.64 1653.54,881.89 1653.54,724.41 1633.86,704.72 1633.86,685.04 1645.67,673.23 1645.67,543.31 1877.95,311.02 v2(1877.95,279.53)
  Bottom Layer w7.87: v2(1877.95,279.53) HDR_B1.49@1877.96,338.58
IO22: HDR_B1.51 U4.AE17 | length 924.8
  Top Layer w5: U4.AE17@1661.42,1019.68 1681.1,1000 1681.1,917.32 1681.1,905.51 1681.1,889.76 1665.35,874.02 1665.35,720.47 1681.1,704.72 1681.1,685.04 1669.29,673.23 1669.29,551.18 1909.45,311.02 v2(1909.45,279.53)
  Bottom Layer w7.87: v2(1909.45,279.53) HDR_B1.51@1909.45,338.58
IO23: HDR_B1.53 U4.AE18 | length 918.3
  Top Layer w5: U4.AE18@1700.79,1019.68 1720.47,1000 1720.47,917.32 1720.47,905.51 1720.47,724.41 1696.85,700.79 1696.85,685.04 1708.66,673.23 1708.66,543.31 1940.95,311.02 v2(1940.95,279.53)
  Bottom Layer w7.87: v2(1940.95,279.53) HDR_B1.53@1940.95,338.58
IO24: HDR_B1.55 U4.AF19 | length 862.6
  Top Layer w5: U4.AF19@1740.16,980.31 1740.16,917.32 1740.16,905.51 1740.16,681.1 1732.28,673.23 1732.28,551.18 1972.44,311.02 v2(1972.44,279.53)
  Bottom Layer w7.87: v2(1972.44,279.53) HDR_B1.55@1972.44,338.58
IO25: HDR_B1.57 U4.AE19 | length 908.5
  Top Layer w5: U4.AE19@1740.16,1019.68 1759.84,1000 1759.84,917.32 1759.84,905.51 1759.84,775.59 1759.84,685.04 1771.65,673.23 1771.65,543.31 2003.94,311.02 v2(2003.94,279.53)
  Bottom Layer w7.87: v2(2003.94,279.53) HDR_B1.57@2003.94,338.58
IO26: HDR_B1.59 U4.AF20 | length 875.6
  Top Layer w5: U4.AF20@1779.53,980.31 1779.53,917.32 1779.53,905.51 1779.53,724.41 1807.09,696.85 1807.09,685.04 1795.27,673.23 1795.27,551.18 2035.43,311.02 v2(2035.43,279.53)
  Bottom Layer w7.87: v2(2035.43,279.53) HDR_B1.59@2035.44,338.58
IO27: HDR_B1.61 U4.AE20 | length 934.6
  Top Layer w5: U4.AE20@1779.53,1019.68 1799.21,1000 1799.21,964.57 1818.9,944.88 1818.9,917.32 1818.9,905.51 1799.21,885.83 1799.21,732.28 1818.9,712.6 1818.9,688.98 1834.64,673.23 1834.64,543.31 2066.93,311.02 v2(2066.93,279.53)
  Bottom Layer w7.87: v2(2066.93,279.53) HDR_B1.61@2066.93,338.58
IO28: HDR_B1.63 U4.AF21 | length 898.5
  Top Layer w5: U4.AF21@1818.9,980.31 1818.9,960.63 1830.71,948.82 1830.71,917.32 1830.71,905.51 1830.71,893.7 1814.96,877.95 1814.96,751.97 1870.08,696.85 1870.08,685.04 1858.27,673.23 1858.27,551.18 2098.43,311.02 v2(2098.43,279.53)
  Bottom Layer w7.87: v2(2098.43,279.53) HDR_B1.63@2098.43,338.58
IO29: HDR_B1.65 U4.AE21 | length 937.8
  Top Layer w5: U4.AE21@1818.9,1019.68 1838.58,1000 1838.58,996.06 1838.58,964.57 1838.58,960.63 1842.52,956.69 1842.52,917.32 1842.52,905.51 1842.52,881.89 1834.65,874.02 1830.71,870.08 1830.71,779.53 1850.39,759.84 1885.83,724.41 1885.83,685.04 1897.64,673.23 1897.64,543.31 2129.92,311.02 v2(2129.92,279.53)
  Bottom Layer w7.87: v2(2129.92,279.53) HDR_B1.65@2129.92,338.58
IO30: HDR_B1.67 U4.AF22 | length 898.5
  Top Layer w5: U4.AF22@1858.27,980.31 1858.27,964.57 1854.33,960.63 1854.33,917.32 1854.33,905.51 1854.33,881.89 1877.95,858.27 1877.95,751.97 1933.07,696.85 1933.07,685.04 1921.26,673.23 1921.26,551.18 2161.42,311.02 v2(2161.42,279.53)
  Bottom Layer w7.87: v2(2161.42,279.53) HDR_B1.67@2161.42,338.58
IO31: HDR_B1.69 U4.AE22 | length 937.8
  Top Layer w5: U4.AE22@1858.27,1019.68 1877.95,1000 1877.95,972.44 1925.2,925.2 1925.2,917.32 1925.2,905.51 1925.2,724.41 1948.82,700.79 1948.82,685.04 1960.63,673.23 1960.63,543.31 2192.91,311.02 v2(2192.91,279.53)
  Bottom Layer w7.87: v2(2192.91,279.53) HDR_B1.69@2192.92,338.58
IO32: HDR_B1.71 U4.AF23 | length 905
  Top Layer w5: U4.AF23@1897.64,980.31 1897.64,976.38 1937.01,937.01 1937.01,917.32 1937.01,905.51 1937.01,755.91 1996.06,696.85 1996.06,685.04 1984.25,673.23 1984.25,551.18 2224.41,311.02 v2(2224.41,279.53)
  Bottom Layer w7.87: v2(2224.41,279.53) HDR_B1.71@2224.41,338.58
IO33: HDR_B1.73 U4.AE23 | length 947.6
  Top Layer w5: U4.AE23@1897.64,1019.68 1917.32,1000 1917.32,972.44 1948.82,940.95 1948.82,917.32 1948.82,905.51 1948.82,763.78 2011.81,700.79 2011.81,685.04 2023.62,673.23 2023.62,543.31 2255.91,311.02 v2(2255.91,279.53)
  Bottom Layer w7.87: v2(2255.91,279.53) HDR_B1.73@2255.91,338.58
IO34: HDR_B1.75 U4.AF24 | length 914.8
  Top Layer w5: U4.AF24@1937.01,980.31 1937.01,976.38 1960.63,952.76 1960.63,917.32 1960.63,905.51 1960.63,795.28 2059.05,696.85 2059.05,685.04 2047.24,673.23 2047.24,551.18 2287.4,311.02 v2(2287.4,279.53)
  Bottom Layer w7.87: v2(2287.4,279.53) HDR_B1.75@2287.41,338.58
IO35: HDR_B1.77 U4.AE24 | length 957.4
  Top Layer w5: U4.AE24@1937.01,1019.68 1956.69,1000 1956.69,972.44 1972.44,956.69 1972.44,917.32 1972.44,905.51 1972.44,803.15 2074.8,700.79 2074.8,685.04 2086.61,673.23 2086.61,543.31 2318.9,311.02 v2(2318.9,279.53)
  Bottom Layer w7.87: v2(2318.9,279.53) HDR_B1.77@2318.9,338.58
KBCLOCK: HDR_T1.26 U4.A16 | length 843
  Top Layer w5: v2(1500,2665.35) 1500,2452.76 1645.67,2307.09 1645.67,2271.65 1637.8,2263.78 1637.8,2074.8 1606.3,2043.31 1606.3,2039.37 1606.3,2027.56 1606.3,1996.06 1622.05,1980.32 U4.A16@1622.05,1964.57
  Bottom Layer w7.87: HDR_T1.26@1500,2606.3 v2(1500,2665.35)
KBDATA: HDR_T1.28 U4.B16 | length 945.9
  Top Layer w5: v2(1531.5,2688.98) 1531.5,2515.75 1531.5,2440.94 1669.29,2303.15 1669.29,2271.65 1677.17,2263.78 1677.17,2240.16 1649.61,2212.6 1649.61,2070.87 1622.05,2043.31 1622.05,2039.37 1622.05,2027.56 1622.05,2000 1641.73,1980.32 1641.73,1944.88 U4.B16@1622.05,1925.2
  Bottom Layer w7.87: HDR_T1.28@1531.5,2606.3 v2(1531.5,2688.98)
LED0: HDR_B1.6 U4.AD6 | length 483.7
  Top Layer w7.87: v1(1208.66,1039.37) U4.AD6@1228.35,1059.05
  MidLayer1 w5: v2(1185.04,665.35) 1185.04,696.85 1192.91,704.72 1192.91,870.08 1177.17,885.83 1177.17,905.51 1177.17,917.32 1177.17,977.36 1208.66,1008.86 v1(1208.66,1039.37)
  Bottom Layer w7.87: HDR_B1.6@1185.04,606.3 v2(1185.04,665.35)
LED1: HDR_B1.8 U4.AC7 | length 532.9
  Top Layer w7.87: v1(1248.03,1078.74) U4.AC7@1267.72,1098.43
  MidLayer1 w5: v2(1216.54,688.98) 1216.54,866.14 1192.91,889.76 1192.91,905.51 1192.91,917.32 1192.91,933.07 1220.47,960.63 1220.47,1015.75 1228.35,1023.62 1228.35,1059.05 v1(1248.03,1078.74)
  Bottom Layer w7.87: HDR_B1.8@1216.54,606.3 v2(1216.54,688.98)
LED2: HDR_B1.10 U4.AC8 | length 630.8
  Top Layer w7.87: v1(1287.4,1078.74) U4.AC8@1307.09,1098.43
  MidLayer1 w5: v2(1248.03,665.35) 1248.03,877.95 1267.72,897.64 1267.72,905.51 1267.72,917.32 1267.72,1059.05 ; 1267.72,944.88 1267.72,1059.05 ; v1(1287.4,1078.74) 1267.72,1059.05
  Bottom Layer w7.87: HDR_B1.10@1248.03,606.3 v2(1248.03,665.35)
LED3: HDR_B1.12 U4.AD8 | length 464.2
  Top Layer w7.87: v1(1287.4,1039.37) U4.AD8@1307.09,1059.05
  MidLayer1 w5: v2(1279.53,688.98) 1279.53,889.76 1287.4,897.64 1287.4,905.51 1287.4,917.32 v1(1287.4,1039.37)
  Bottom Layer w7.87: HDR_B1.12@1279.53,606.3 v2(1279.53,688.98)
LED4: HDR_B1.14 U4.AC9 | length 519.8
  Top Layer w7.87: v1(1326.77,1078.74) U4.AC9@1346.46,1098.43
  MidLayer1 w5: v2(1311.02,665.35) 1311.02,736.22 1295.28,751.97 1295.28,885.83 1307.09,897.64 1307.09,905.51 1307.09,917.32 1307.09,1059.05 v1(1326.77,1078.74)
  Bottom Layer w7.87: HDR_B1.14@1311.03,606.3 v2(1311.02,665.35)
LED5: HDR_B1.16 U4.AD9 | length 467.4
  Top Layer w7.87: v1(1326.77,1039.37) U4.AD9@1346.46,1059.05
  MidLayer1 w5: v1(1326.77,1039.37) 1326.77,917.32 1326.77,905.51 1326.77,901.57 1342.52,885.83 v2(1342.52,688.98)
  Bottom Layer w7.87: HDR_B1.16@1342.52,606.3 v2(1342.52,688.98)
LED6: HDR_B1.18 U4.AD10 | length 464.2
  Top Layer w7.87: v1(1366.14,1039.37) U4.AD10@1385.83,1059.05
  MidLayer1 w5: v1(1366.14,1039.37) 1366.14,944.88 1366.14,917.32 1366.14,905.51 1366.14,696.85 1374.02,688.98 v2(1374.02,665.35)
  Bottom Layer w7.87: HDR_B1.18@1374.02,606.3 v2(1374.02,665.35)
LED7: HDR_B1.20 U4.AC10 | length 516.6
  Top Layer w7.87: v1(1366.14,1078.74) U4.AC10@1385.83,1098.43
  MidLayer1 w5: v1(1366.14,1078.74) 1385.82,1059.05 1385.82,917.32 1385.83,905.51 1385.83,755.91 1405.51,736.22 v2(1405.51,688.98)
  Bottom Layer w7.87: HDR_B1.20@1405.51,606.3 v2(1405.51,688.98)
LED_PGM: LED1.2 U2.4 | length 255.9
  Top Layer w7.87: LED1.2@1295.28,165.35 1301.18,165.35 1425.2,165.35 v1(1468.5,122.05)
  Bottom Layer w7.87: U2.4@1431.51,112.95 1435.5,111.55 U2.4@1440.94,109.65 ; U2.4@1433.07,125.98 1435.04,125.98 1438.97,122.05 v1(1468.5,122.05) ; U2.4@1440.94,104.33 U2.4@1440.94,109.65 ; U2.4@1440.94,122.05 1440.94,110.24 U2.4@1440.94,109.65
LED_PWR: LED2.1 R2.2 | length 102.8
  Top Layer w15.75: v1(1893.7,169.29) LED2.1@1935.04,169.29 LED2.1@1937.01,169.29
  Bottom Layer w15.75: v1(1893.7,169.29) R2.2@1953.23,169.29
LX: L1.1 U5.1 U5.3 U5.14 U5.16 | length 721.5
  Top Layer w15.75: U5.16@2592.58,1633.25 2660.81,1633.25 v3@2669.29,1641.73 ; U5.14@2592.58,1683.25 2651.4,1683.25 ; 2653.54,1681.1 2651.4,1683.25 ; v3@2669.29,1677.17 2663.21,1683.25 2651.4,1683.25 ; 2748.03,1641.73 2756.52,1633.25 U5.1@2824.58,1633.25 ; 2748.03,1677.17 2754.11,1683.25 U5.3@2824.58,1683.25
  Bottom Layer w78.74: 2381.89,1944.88 2653.54,1673.23 v3@2669.29,1673.23
  other v3: 2661.42,1641.73 2690.96,1641.73 2720.5,1641.73 2661.42,1669.29 2690.96,1669.29 2720.5,1669.29 2661.42,1696.85 2690.96,1696.85 2720.5,1696.85
M0: R14.2 U4.AE3 | length 281.1
  Top Layer w5: v1(995.9,905.5) 1028.89,938.49 1064.47,938.49 1090.55,964.57 1090.55,1000 U4.AE3@1110.24,1019.68
  Bottom Layer w5: R14.2@907.01,881.89 972.29,881.89 v1(995.9,905.5)
M1: R13.2 U4.AC3 | length 262.9
  Top Layer w7.87: v1(1090.55,1078.74) U4.AC3@1110.24,1098.43
  MidLayer1 w5: v1(940.94,968.5) 1000,1027.56 1039.37,1027.56 v1(1090.55,1078.74) ; v1@942.91,968.5 v1@942.91,970.47
  Bottom Layer w5: R13.2@907.01,968.5 v1(940.94,968.5) v1@940.94,964.57
M2: R11.2 U4.AF3 | length 268.1
  Top Layer w5: v1(1051.1,911.7) 1091.8,911.7 1104.17,924.07 1104.17,954.57 1110.24,960.63 U4.AF3@1110.24,980.31
  Bottom Layer w5: R11.2@907.01,926.69 R11.2@907.01,925.2 1012.1,925.2 1025.59,911.7 v1(1051.1,911.7)
MOUSECLOCK: HDR_T1.30 U4.A17 | length 839.7
  Top Layer w5: v2(1562.99,2665.35) 1562.99,2437.01 1708.66,2291.34 1708.66,2271.65 1696.85,2259.84 1696.85,2232.28 1661.42,2196.85 1661.42,2039.37 1661.42,2027.56 U4.A17@1661.42,1964.57
  Bottom Layer w7.87: HDR_T1.30@1562.99,2606.3 v2(1562.99,2665.35)
MOUSEDATA: HDR_T1.32 U4.B17 | length 957.3
  Top Layer w5: v2(1594.49,2688.98) 1594.49,2631.89 1576.77,2614.17 1576.77,2442.91 1732.28,2287.4 1732.28,2271.65 1744.09,2259.84 1744.09,2248.03 1692.91,2196.85 1692.91,2039.37 1692.91,2027.56 1692.91,2011.81 1681.1,2000 1681.1,1944.88 U4.B17@1661.42,1925.2
  Bottom Layer w7.87: HDR_T1.32@1594.49,2606.3 v2(1594.49,2688.98)
NetC127_1: C127.1 U6.6 | length 96.1
  Top Layer w5: U6.6@1940.94,2496.06 1972.44,2496.06 1996.06,2519.68 1996.06,2538.38 C127.1@1987.2,2547.24
NetLED1_1: LED1.1 R1.2 | length 87.1
  Top Layer w7.87: v1(1181.1,169.29) LED1.1@1222.44,169.29
  Bottom Layer w7.87: v1(1181.1,169.29) R1.2@1226.85,169.29
NetR21_2: R21.2 R22.1 | length 60
  Top Layer w13.78: R21.2@2910.94,1866.14 R22.1@2970.94,1866.14
NetRN1_8: RN1.8 RN4.5 | length 91.3
  Bottom Layer w5: RN1.8@1688.58,3271.65 RN4.5@1779.53,3271.65 RN4.5@1779.92,3271.65
NetRN2_8: RN2.8 RN6.5 | length 91.3
  Bottom Layer w5: RN2.8@1393.3,3271.65 RN6.5@1483.28,3271.66 RN6.5@1484.64,3271.65
NEXUS_TCK: HDR_T1.82 U4.P21 | length 1792
  Top Layer w7.87: U4.P21@1818.9,1452.76 v1(1838.58,1433.07)
  MidLayer3 w5: v1(1838.58,1433.07) 1858.27,1413.39 2078.74,1413.39 2090.55,1413.39 2106.3,1429.13 2106.3,1472.44 2129.92,1496.06 2181.1,1496.06 2287.4,1602.36 2287.4,2027.56 2433.07,2173.23 2433.07,2263.78 2425.2,2271.65 2425.2,2381.89 2381.89,2425.2 v2(2381.89,2665.35)
  Bottom Layer w7.87: HDR_T1.82@2381.89,2606.3 v2(2381.89,2665.35)
NEXUS_TDI: HDR_T1.84 U4.R21 | length 1873.3
  Top Layer w7.87: U4.R21@1818.9,1413.39 v1(1838.58,1393.7)
  MidLayer3 w5: v1(1838.58,1393.7) 1858.27,1374.02 2007.87,1374.02 2031.5,1397.64 2078.74,1397.64 2090.55,1397.64 2133.86,1397.64 2194.88,1458.66 2194.88,1494.09 2299.21,1598.43 2299.21,2023.62 2444.88,2169.29 2444.88,2251.97 2464.57,2271.65 2464.57,2377.95 2413.38,2429.13 v2(2413.38,2688.98)
  Bottom Layer w7.87: HDR_T1.84@2413.39,2606.3 v2(2413.38,2688.98)
NEXUS_TDO: HDR_T1.76 U4.B23 | length 1007.9
  Top Layer w5: U4.B23@1897.64,1925.2 1917.32,1944.88 1917.32,1984.25 1944.88,2011.81 1944.88,2027.56 1944.88,2039.37 1944.88,2110.24 2074.8,2240.15 2074.8,2259.84 2086.61,2271.65 2287.4,2472.44 2287.4,2661.42 v2(2287.4,2688.98)
  Bottom Layer w7.87: HDR_T1.76@2287.4,2606.3 v2(2287.4,2688.98)
NEXUS_TMS: HDR_T1.80 U4.P19 | length 1867.8
  Top Layer w7.87: U4.P19@1740.16,1452.76 v1@1759.84,1433.07
  MidLayer3 w5: v1(1759.84,1430.12) 1779.53,1452.76 2078.74,1452.76 2090.55,1452.76 2094.49,1456.69 2094.49,1476.38 2125.98,1507.87 2177.17,1507.87 2275.59,1606.3 2275.59,2031.5 2393.7,2149.61 2393.7,2263.78 2401.57,2271.65 2401.57,2366.14 2350.39,2417.33 v2(2350.39,2688.98)
  Bottom Layer w7.87: HDR_T1.80@2350.4,2606.3 v2(2350.39,2688.98)
NFAULT: R24.2 U6.8 | length 239.6
  Top Layer w5: R24.2@1741.65,2637.79 1741.65,2593.35 1788.75,2546.25 U6.8@1917.32,2546.25
ONE_WIRE.PIO2: U1.6
ONE_WIRE_DB_PB: HDR_B1.79 U4.AA8 | length 1949.5
  Top Layer w7.87: v1(1287.4,1157.48) U4.AA8@1307.09,1177.17
  MidLayer3 w5: v1(1287.4,1157.48) 1267.72,1137.79 1267.72,913.38 1267.72,889.76 1251.97,874.02 1251.97,688.98 1267.72,673.23 1267.72,622.05 1562.99,326.77 2334.65,326.77 2350.39,311.02 v2(2350.39,248.03)
  Bottom Layer w7.87: v2(2350.39,248.03) HDR_B1.79@2350.4,338.58
ONE_WIRE_DBID: HDR_T1.92 U1.2 | length 314.2
  Bottom Layer w5: HDR_T1.92@2539.37,2606.3 2539.37,2678.98 2539.37,2805.12 2580.71,2846.46 U1.2@2637.59,2846.45
ONE_WIRE_PIO1: HDR_T1.91 U1.3 | length 1181.7
  MidLayer2 w5: v1(2539.36,2248.03) 2539.36,2220.63 2560,2200 v1(2615,2200)
  Bottom Layer w5: v1(2539.36,2248.03) HDR_T1.91@2539.36,2318.89 ; v1(2615,2200) 2755.12,2200 2787.4,2232.28 2787.4,2562.4 2811.02,2586.02 2811.02,2716.53 2795.27,2732.28 2732.28,2732.28 2708.66,2755.9 2708.66,2877.95 2690.15,2896.45 U1.3@2637.59,2896.45
PROG_B: R15.2 U4.D3 | length 444.2
  Top Layer w7.87: v1(1090.55,1866.14) U4.D3@1110.24,1846.46
  MidLayer1 w5: v1(846.46,2062.99) 846.46,1962.96 901.78,1907.64 1001.81,1907.64 1043.31,1866.14 v1(1090.55,1866.14)
  Bottom Layer w5: R15.2@844.96,2094.48 846.46,2092.99 v1(846.46,2062.99)
REF_1V2: C124.2 U5.10 | length 86.8
  Top Layer w15.75: C124.2@2505.9,1783.46 2506.11,1783.25 U5.10@2592.58,1783.25
REF_CLK: HDR_B1.4 U4.AF14 | length 852.1
  Top Layer w5: v1(1523.62,736.22) 1547.24,759.84 1547.24,870.08 1543.31,874.02 1543.31,917.32 U4.AF14@1543.31,980.31
  MidLayer1 w5: v2(1153.54,688.98) 1153.54,665.35 1177.17,641.73 1511.81,641.73 1551.18,681.1 1551.18,708.66 v1(1523.62,736.22)
  Bottom Layer w7.87: HDR_B1.4@1153.55,606.3 v2(1153.54,688.98)
RS232_CTS: HDR_T1.22 U4.A15 | length 862.6
  Top Layer w5: v2(1437.01,2665.35) 1437.01,2472.44 1582.68,2326.77 1582.68,2271.65 1570.87,2259.84 1570.87,2251.97 1570.87,2248.03 1614.17,2204.72 1614.17,2094.49 1574.8,2055.12 1574.8,2039.37 1574.8,2027.56 1574.8,1988.19 1582.68,1980.32 U4.A15@1582.68,1964.57
  Bottom Layer w7.87: HDR_T1.22@1437.01,2606.3 v2(1437.01,2665.35)
RS232_RTS: HDR_T1.18 U4.A12 | length 843
  Top Layer w5: v2(1374.01,2665.35) 1374.01,2472.44 1519.68,2326.77 1519.68,2271.65 1507.87,2259.84 1507.87,2251.97 1500,2244.09 1500,2082.68 1472.44,2055.12 1472.44,2039.37 1472.44,2027.56 1472.44,1988.19 1464.57,1980.31 U4.A12@1464.57,1964.57
  Bottom Layer w7.87: HDR_T1.18@1374.02,2606.3 v2(1374.01,2665.35)
RS232_RX: HDR_T1.24 U4.B15 | length 939.4
  Top Layer w5: v2(1468.5,2688.98) 1468.5,2464.57 1606.3,2326.77 1606.3,2271.65 1625.98,2251.97 1625.98,2086.61 1590.55,2051.18 1590.55,2039.37 1590.55,2027.56 1590.55,1992.13 1602.36,1980.32 1602.36,1944.88 U4.B15@1582.68,1925.2
  Bottom Layer w7.87: HDR_T1.24@1468.5,2606.3 v2(1468.5,2688.98)
RS232_TX: HDR_T1.20 U4.A14 | length 913.1
  Top Layer w5: v2(1405.51,2688.98) 1405.51,2464.57 1543.31,2326.77 1543.31,2271.65 1555.12,2259.84 1555.12,2244.09 1602.36,2196.85 1602.36,2098.43 1543.31,2039.37 1543.31,2027.56 U4.A14@1543.31,1964.57
  Bottom Layer w7.87: HDR_T1.20@1405.51,2606.3 v2(1405.51,2688.98)
SCL: HDR_B1.5 U4.AA7 | length 1000.7
  Top Layer w7.87: v1(1248.03,1157.48) U4.AA7@1267.72,1177.17
  MidLayer3 w5: v2(1185.04,279.53) 1185.04,633.86 1204.72,653.54 1204.72,673.23 1192.91,685.04 1192.91,905.51 1192.91,917.32 1192.91,992.13 1228.35,1027.56 1228.34,1137.79 v1(1248.03,1157.48)
  Bottom Layer w7.87: v2(1185.04,279.53) HDR_B1.5@1185.04,338.58
SDA: HDR_B1.3 U4.AA6 | length 987.7
  Top Layer w7.87: v1(1208.66,1157.48) U4.AA6@1228.35,1177.17
  MidLayer3 w5: v2(1153.54,279.53) 1153.54,661.42 1177.17,685.04 1177.17,905.51 1177.17,917.32 1177.16,1015.75 1188.98,1027.56 1188.97,1137.79 v1(1208.66,1157.48)
  Bottom Layer w7.87: v2(1153.54,279.53) HDR_B1.3@1153.55,338.58
SLEEP_N: HDR_T1.93
SPI_CLK: HDR_T1.46 U4.E13 | length 1109.1
  Top Layer w7.87: v1(1484.25,1826.77) U4.E13@1503.94,1807.09
  MidLayer2 w5: v1(1484.25,1826.77) 1503.94,1846.46 1503.94,2027.56 1503.94,2039.37 1503.94,2043.31 1515.75,2055.12 1547.24,2055.12 1681.1,2188.98 1712.6,2188.98 1740.16,2216.54 1740.16,2263.78 1728.35,2275.59 1728.35,2295.28 1814.96,2381.89 v2(1814.96,2665.35)
  Bottom Layer w7.87: HDR_T1.46@1814.96,2606.3 v2(1814.96,2665.35)
SPI_DIN: HDR_T1.44 U4.H12 | length 1305
  Top Layer w7.87: v1(1444.88,1708.66) U4.H12@1464.57,1688.98
  MidLayer2 w5: v1(1444.88,1708.66) 1464.56,1728.35 1464.56,2027.56 1464.57,2039.37 1464.57,2051.18 1444.88,2070.87 1444.88,2169.29 1507.87,2232.28 1606.3,2232.28 1646.13,2272.11 1649.61,2275.59 1649.61,2318.9 1704.72,2374.02 1704.72,2610.24 v2(1783.46,2688.98)
  Bottom Layer w7.87: HDR_T1.44@1783.47,2606.3 v2(1783.46,2688.98)
SPI_DOUT: HDR_T1.50 U4.H15 | length 1199
  Top Layer w7.87: U4.H15@1582.68,1688.98 v1(1602.36,1708.66)
  MidLayer2 w5: v1(1602.36,1708.66) 1582.68,1728.35 1582.68,2027.56 1582.68,2039.37 1582.68,2051.18 1696.85,2165.35 1728.35,2165.35 1803.15,2240.16 1803.15,2263.78 1795.28,2271.65 1795.28,2291.34 1877.95,2374.01 v2(1877.95,2665.35)
  Bottom Layer w7.87: HDR_T1.50@1877.95,2606.3 v2(1877.95,2665.35)
SPI_MODE: HDR_T1.52 U4.E15 | length 1116.6
  Top Layer w7.87: U4.E15@1582.68,1807.09 v1(1602.36,1826.77)
  MidLayer2 w5: v1(1602.36,1826.77) 1622.05,1846.46 1622.05,2027.56 1622.05,2039.37 1622.05,2067.91 1707.68,2153.54 1736.22,2153.54 1822.83,2240.16 1822.83,2259.84 1909.45,2346.46 v2(1909.45,2688.98)
  Bottom Layer w7.87: HDR_T1.52@1909.45,2606.3 v2(1909.45,2688.98)
SPI_SEL: HDR_T1.48 U4.E14 | length 1168.5
  Top Layer w7.87: U4.E14@1543.31,1807.09 v1(1562.99,1826.77)
  MidLayer2 w5: v1(1562.99,1826.77) 1543.31,1846.46 1543.31,1874.02 1515.75,1901.57 1515.75,2027.56 1515.75,2039.37 1519.68,2043.31 1555.12,2043.31 1688.98,2177.17 1720.47,2177.17 1763.78,2220.47 1763.78,2263.78 1775.59,2275.59 1775.59,2287.4 1846.46,2358.27 v2(1846.46,2688.98)
  Bottom Layer w7.87: HDR_T1.48@1846.46,2606.3 v2(1846.46,2688.98)
SRAM1_A0: U4.AC18 U10.1 | length 1141.2
  Top Layer w7.87: U4.AC18@1700.79,1098.43 v1(1720.47,1078.74)
  MidLayer1 w5: v1(1720.47,1078.74) 1740.16,1059.05 1740.16,917.32 1740.16,905.51 1740.16,889.76 1748.03,881.89 1748.03,846.46 1866.14,728.35 v1(2523.62,728.35)
  Bottom Layer w5: U10.1@2478.44,728.34 v1(2523.62,728.35)
SRAM1_A1: U4.AC19 U10.2 | length 1254.9
  Top Layer w7.87: U4.AC19@1740.16,1098.43 v1(1759.84,1078.74)
  MidLayer1 w5: v1(1759.84,1078.74) 1779.53,1059.05 ; 1779.53,944.88 1779.53,1059.05 ; v1(2547.24,759.84) 1866.14,759.84 1779.53,846.46 1779.53,905.51 1779.53,917.32 1779.53,1059.05
  Bottom Layer w5: U10.2@2478.44,759.83 v1(2547.24,759.84)
SRAM1_A2: U4.AD21 U10.3 | length 955
  Top Layer w7.87: U4.AD21@1818.9,1059.05 v1(1838.58,1039.37)
  MidLayer1 w5: v1(1838.58,1039.37) 1838.58,1008.86 1830.71,1000.98 1830.71,955.71 1830.71,917.32 1830.71,905.51 1830.71,897.64 1937.01,791.34 v1(2523.62,791.34)
  Bottom Layer w5: U10.3@2478.44,791.33 v1(2523.62,791.34)
SRAM1_A3: U4.AD22 U10.4 | length 967.5
  Top Layer w7.87: U4.AD22@1858.27,1059.05 v1(1877.95,1039.37)
  MidLayer1 w5: v1(1877.95,1039.37) 1877.95,992.13 1854.33,968.5 1854.33,917.32 1854.33,905.51 1937.01,822.83 v1(2547.24,822.83)
  Bottom Layer w5: U10.4@2478.44,822.83 v1(2547.24,822.83)
SRAM1_A4: U4.AD23 U10.5 | length 825.2
  Top Layer w7.87: U4.AD23@1897.64,1059.05 v1(1917.32,1039.37)
  MidLayer1 w5: v1(1917.32,1039.37) 1972.44,984.25 1972.44,917.32 1972.44,905.51 1972.44,866.14 1984.25,854.33 v1(2523.62,854.33)
  Bottom Layer w5: U10.5@2478.44,854.32 v1(2523.62,854.33)
SRAM1_A5: U4.Y16 U10.18 | length 1580.2
  Top Layer w7.87: U4.Y16@1622.05,1216.54 v1(1641.73,1196.85)
  MidLayer4 w5: v1(1641.73,1196.85) 1661.42,1181.1 1661.42,1027.56 1661.42,948.82 1681.1,929.13 1681.1,917.32 1681.1,905.51 1795.28,791.34 1874.02,791.34 1914.37,831.69 2193.9,831.69 2299.21,937.01 2299.21,1122.05 2440.93,1263.77 v1(2523.83,1263.77)
  Bottom Layer w5: U10.18@2478.44,1263.77 v1@2527.77,1263.77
